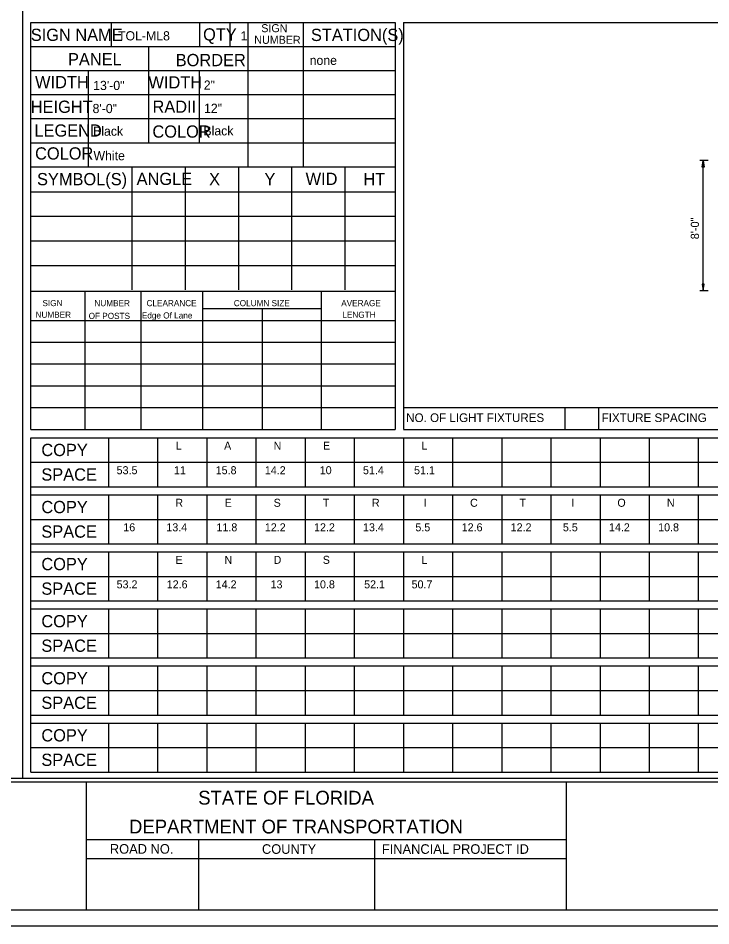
# Model space of a CAD drawing. Extents: x 122633 to 124574, y -23288 to -22025.
# Drawn here: x 123601 to 124110, y -23272 to -22604 of the extents above; entities that cross this region are included whole.
import ezdxf

# ---------------------------------------------------------------- set-up
doc = ezdxf.new("R2010")
doc.units = 0
for name, color, linetype in [('GSDims', 7, 'Continuous'), ('GSSign', 7, 'Continuous'), ('PlotBorder_dp', 7, 'Continuous'), ('SheetBorder_dp', 7, 'Continuous'), ('SheetLines_dp', 7, 'Continuous'), ('SheetLinesMisc2_dp', 7, 'Continuous'), ('TextMinor', 7, 'Continuous'), ('TextMisc', 7, 'Continuous')]:
    doc.layers.add(name, color=color, linetype=linetype)

msp = doc.modelspace()

# ---------------------------------------------------------------- linework, layer by layer
at = {"layer": 'GSDims'}
for p, q in [((124107.69, -22708.87), (124101.44, -22708.87)), ((124103.94, -22804.87), (124103.94, -22708.87)), ((124107.69, -22708.87), (124107.69, -22708.87)), ((124107.69, -22804.87), (124101.44, -22804.87)), ((124107.69, -22804.87), (124107.69, -22804.87))]:
    msp.add_line(p, q, dxfattribs=at)
for points in [[(124103.94, -22708.87), (124104.77, -22713.87), (124103.11, -22713.87)], [(124103.94, -22804.87), (124104.77, -22799.87), (124103.11, -22799.87)]]:
    msp.add_lwpolyline(points, close=True, dxfattribs=at)
at = {"layer": 'PlotBorder_dp'}
msp.add_lwpolyline([(122633.11, -23271.62), (124574.11, -23271.62), (124574.11, -22024.68), (122633.11, -22024.68)], close=True, dxfattribs=at)
at = {"layer": 'SheetBorder_dp'}
for p, q in [((122697.81, -23165.75), (124509.41, -23165.75)), ((122697.81, -23259.86), (124509.41, -23259.86))]:
    msp.add_line(p, q, dxfattribs=at)
at = {"layer": 'SheetLines_dp'}
for p, q in [((123650.66, -23165.75), (123650.66, -23259.86)), ((124003.57, -23259.86), (124003.57, -23165.75)), ((123650.66, -23208.1), (124003.57, -23208.1)), ((123733.01, -23208.1), (123733.01, -23259.86)), ((123862.41, -23208.1), (123862.41, -23259.86)), ((123650.66, -23222.22), (124003.57, -23222.22))]:
    msp.add_line(p, q, dxfattribs=at)
at = {"layer": 'SheetLinesMisc2_dp'}
for p, q in [((123603.64, -22039.22), (123603.64, -23162.98)), ((123609.83, -22906.62), (123609.83, -22607.55)), ((123609.83, -22607.55), (123877.5, -22607.55)), ((123668.83, -22607.55), (123668.83, -22625.22)), ((123733.89, -22607.55), (123733.89, -22625.22)), ((123756.12, -22607.55), (123756.12, -22625.22)), ((123769.37, -22607.55), (123769.37, -22713.54)), ((123810.1, -22607.55), (123810.1, -22713.54)), ((123877.5, -22607.55), (123877.5, -22906.62)), ((123883.65, -22607.55), (124497.63, -22607.55)), ((123883.65, -22607.55), (123883.65, -22906.19)), ((123609.83, -22625.22), (123877.5, -22625.22)), ((123696.33, -22625.22), (123696.33, -22696.07)), ((123609.83, -22642.88), (123877.5, -22642.88)), ((123652.13, -22642.88), (123652.13, -22713.54)), ((123733.66, -22643.07), (123733.66, -22696.07)), ((123609.83, -22660.55), (123877.5, -22660.55)), ((123609.83, -22678.21), (123877.5, -22678.21)), ((123609.83, -22695.88), (123709.1, -22695.88)), ((123696.33, -22696.07), (123769.37, -22696.07)), ((123769.37, -22695.88), (123877.5, -22695.88)), ((123609.83, -22713.54), (123877.5, -22713.54)), ((123684.16, -22713.89), (123684.16, -22804.08)), ((123723.27, -22713.89), (123723.27, -22804.08)), ((123762.39, -22713.89), (123762.39, -22804.08)), ((123801.49, -22713.89), (123801.49, -22804.08)), ((123840.61, -22713.89), (123840.61, -22804.08)), ((123609.88, -22731.93), (123877.5, -22731.93)), ((123609.88, -22749.97), (123877.5, -22749.97)), ((123609.88, -22768), (123877.5, -22768)), ((123609.88, -22786.04), (123877.5, -22786.04)), ((123609.83, -22804.95), (123877.5, -22804.95)), ((123649.54, -22804.95), (123649.54, -22906.62)), ((123690.6, -22804.95), (123690.6, -22906.62)), ((123735.93, -22804.95), (123735.93, -22906.62)), ((123823.22, -22804.95), (123823.22, -22906.62)), ((123735.93, -22817.88), (123823.16, -22817.88)), ((123779.75, -22817.88), (123779.75, -22906.62)), ((123609.83, -22826.5), (123877.5, -22826.5)), ((123609.83, -22842.52), (123877.5, -22842.52)), ((123609.83, -22858.55), (123877.5, -22858.55)), ((123609.83, -22874.57), (123877.5, -22874.57)), ((123609.83, -22890.6), (123877.5, -22890.6)), ((123883.65, -22890.59), (124497.63, -22890.59)), ((124002.24, -22890.59), (124002.24, -22906.61)), ((124027.09, -22890.59), (124027.09, -22906.61)), ((123609.83, -22906.62), (123877.5, -22906.62)), ((123883.65, -22906.19), (123883.65, -22906.59)), ((123883.65, -22906.61), (124497.63, -22906.61)), ((123609.8, -22912.77), (124497.63, -22912.77)), ((123609.8, -23158.6), (123609.8, -22912.77)), ((123666.96, -22912.77), (123666.96, -22948.85)), ((123703.08, -22912.77), (123703.08, -22948.85)), ((123739.18, -22912.77), (123739.18, -22948.85)), ((123775.3, -22912.77), (123775.3, -22948.85)), ((123811.43, -22912.77), (123811.43, -22948.85)), ((123847.54, -22912.77), (123847.54, -22948.85)), ((123883.65, -22912.77), (123883.65, -22948.85)), ((123919.77, -22912.77), (123919.77, -22948.85)), ((123955.89, -22912.77), (123955.89, -22948.85)), ((123992, -22912.77), (123992, -22948.85)), ((124028.13, -22912.77), (124028.13, -22948.85)), ((124064.23, -22912.77), (124064.23, -22948.85)), ((124100.35, -22912.77), (124100.35, -22948.85)), ((123609.8, -22930.8), (124497.63, -22930.8)), ((123609.8, -22948.85), (124497.63, -22948.85)), ((123609.8, -22954.73), (124497.63, -22954.73)), ((123666.96, -22954.73), (123666.96, -22990.8)), ((123703.08, -22954.73), (123703.08, -22990.8)), ((123739.18, -22954.73), (123739.18, -22990.8)), ((123775.3, -22954.73), (123775.3, -22990.8)), ((123811.43, -22954.73), (123811.43, -22990.8)), ((123847.54, -22954.73), (123847.54, -22990.8)), ((123883.65, -22954.73), (123883.65, -22990.8)), ((123919.77, -22954.73), (123919.77, -22990.8)), ((123955.89, -22954.73), (123955.89, -22990.8)), ((123992, -22954.73), (123992, -22990.8)), ((124028.13, -22954.73), (124028.13, -22990.8)), ((124064.23, -22954.73), (124064.23, -22990.8)), ((124100.35, -22954.73), (124100.35, -22990.8)), ((123609.8, -22972.77), (124497.63, -22972.77)), ((123609.8, -22990.8), (124497.63, -22990.8)), ((123609.8, -22996.68), (124497.63, -22996.68)), ((123666.96, -22996.68), (123666.96, -23032.75)), ((123703.08, -22996.68), (123703.08, -23032.75)), ((123739.18, -22996.68), (123739.18, -23032.75)), ((123775.3, -22996.68), (123775.3, -23032.75)), ((123811.43, -22996.68), (123811.43, -23032.75)), ((123847.54, -22996.68), (123847.54, -23032.75)), ((123883.65, -22996.68), (123883.65, -23032.75)), ((123919.77, -22996.68), (123919.77, -23032.75)), ((123955.89, -22996.68), (123955.89, -23032.75)), ((123992, -22996.68), (123992, -23032.75)), ((124028.13, -22996.68), (124028.13, -23032.75)), ((124064.23, -22996.68), (124064.23, -23032.75)), ((124100.35, -22996.68), (124100.35, -23032.75)), ((123609.8, -23014.71), (124497.63, -23014.71)), ((123609.8, -23032.75), (124497.63, -23032.75)), ((123609.8, -23038.63), (124497.63, -23038.63)), ((123666.96, -23038.63), (123666.96, -23074.71)), ((123703.08, -23038.63), (123703.08, -23074.71)), ((123739.18, -23038.63), (123739.18, -23074.71)), ((123775.3, -23038.63), (123775.3, -23074.71)), ((123811.43, -23038.63), (123811.43, -23074.71)), ((123847.54, -23038.63), (123847.54, -23074.71)), ((123883.65, -23038.63), (123883.65, -23074.71)), ((123919.77, -23038.63), (123919.77, -23074.71)), ((123955.89, -23038.63), (123955.89, -23074.71)), ((123992, -23038.63), (123992, -23074.71)), ((124028.13, -23038.63), (124028.13, -23074.71)), ((124064.23, -23038.63), (124064.23, -23074.71)), ((124100.35, -23038.63), (124100.35, -23074.71)), ((123609.8, -23056.66), (124497.63, -23056.66)), ((123609.8, -23074.71), (124497.63, -23074.71)), ((123609.8, -23080.59), (124497.63, -23080.59)), ((123666.96, -23080.59), (123666.96, -23116.66)), ((123703.08, -23080.59), (123703.08, -23116.66)), ((123739.18, -23080.59), (123739.18, -23116.66)), ((123775.3, -23080.59), (123775.3, -23116.66)), ((123811.43, -23080.59), (123811.43, -23116.66)), ((123847.54, -23080.59), (123847.54, -23116.66)), ((123883.65, -23080.59), (123883.65, -23116.66)), ((123919.77, -23080.59), (123919.77, -23116.66)), ((123955.89, -23080.59), (123955.89, -23116.66)), ((123992, -23080.59), (123992, -23116.66)), ((124028.13, -23080.59), (124028.13, -23116.66)), ((124064.23, -23080.59), (124064.23, -23116.66)), ((124100.35, -23080.59), (124100.35, -23116.66)), ((123609.8, -23098.63), (124497.63, -23098.63)), ((123609.8, -23116.66), (124497.63, -23116.66)), ((123609.8, -23122.54), (124497.63, -23122.54)), ((123666.96, -23122.54), (123666.96, -23158.6)), ((123703.08, -23122.54), (123703.08, -23158.6)), ((123739.18, -23122.54), (123739.18, -23158.6)), ((123775.3, -23122.54), (123775.3, -23158.6)), ((123811.43, -23122.54), (123811.43, -23158.6)), ((123847.54, -23122.54), (123847.54, -23158.6)), ((123883.65, -23122.54), (123883.65, -23158.6)), ((123919.77, -23122.54), (123919.77, -23158.6)), ((123955.89, -23122.54), (123955.89, -23158.6)), ((123992, -23122.54), (123992, -23158.6)), ((124028.13, -23122.54), (124028.13, -23158.6)), ((124064.23, -23122.54), (124064.23, -23158.6)), ((124100.35, -23122.54), (124100.35, -23158.6)), ((123609.8, -23140.57), (124497.63, -23140.57)), ((123609.8, -23158.6), (124497.63, -23158.6)), ((122701.01, -23162.98), (124506.26, -23162.98))]:
    msp.add_line(p, q, dxfattribs=at)

# ---------------------------------------------------------------- texts
at = {"layer": 'GSDims'}
msp.add_text('8\'-0"', height=6, rotation=90, dxfattribs=at).set_placement((124100.83, -22766.87))
at = {"layer": 'GSSign'}
for s, height, p in [('TOL-ML8', 6.749, (123673.96, -22620.68)), ('1', 6.75, (123764.05, -22620.7)), ('none', 6.749, (123814.77, -22638.7)), ('13\'-0"', 6.749, (123655.71, -22657.16)), ('2"', 6.749, (123736.97, -22656.91)), ('8\'-0"', 6.749, (123655.25, -22674.12)), ('12"', 6.749, (123737.15, -22673.93)), ('Black', 6.749, (123655.63, -22690.76)), ('Black', 6.749, (123736.7, -22690.5)), ('White', 6.749, (123655.93, -22708.81)), ('L', 5.88, (123716.33, -22921.58)), ('A', 5.88, (123751.89, -22921.58)), ('N', 5.88, (123788.29, -22921.58)), ('E', 5.88, (123824.56, -22921.58)), ('L', 5.88, (123896.95, -22921.58)), ('53.5', 5.882, (123672.92, -22939.61)), ('11', 5.882, (123715.07, -22939.61)), ('15.8', 5.882, (123745.73, -22939.61)), ('14.2', 5.882, (123781.85, -22939.61)), ('10', 5.882, (123822.18, -22939.61)), ('51.4', 5.882, (123853.96, -22939.61)), ('51.1', 5.882, (123891.49, -22939.61)), ('R', 5.88, (123716.05, -22963.53)), ('E', 5.88, (123752.31, -22963.53)), ('S', 5.88, (123788.29, -22963.53)), ('T', 5.88, (123824.42, -22963.53)), ('R', 5.88, (123860.54, -22963.53)), ('I', 5.88, (123898.63, -22963.53)), ('C', 5.88, (123932.65, -22963.53)), ('T', 5.88, (123968.92, -22963.53)), ('I', 5.88, (124007, -22963.53)), ('O', 5.88, (124040.89, -22963.53)), ('N', 5.88, (124077.29, -22963.53)), ('16', 5.882, (123677.82, -22981.57)), ('13.4', 5.882, (123709.46, -22981.57)), ('11.8', 5.882, (123746.29, -22981.57)), ('12.2', 5.882, (123781.85, -22981.57)), ('12.2', 5.882, (123817.98, -22981.57)), ('13.4', 5.882, (123853.96, -22981.57)), ('5.5', 5.882, (123892.47, -22981.57)), ('12.6', 5.882, (123926.49, -22981.57)), ('12.2', 5.882, (123962.47, -22981.57)), ('5.5', 5.882, (124000.84, -22981.57)), ('14.2', 5.882, (124034.72, -22981.57)), ('10.8', 5.882, (124070.85, -22981.57)), ('E', 5.88, (123716.19, -23005.49)), ('N', 5.88, (123752.17, -23005.49)), ('D', 5.88, (123788.29, -23005.49)), ('S', 5.88, (123824.42, -23005.49)), ('L', 5.88, (123896.95, -23005.49)), ('53.2', 5.882, (123672.92, -23023.52)), ('12.6', 5.882, (123709.74, -23023.52)), ('14.2', 5.882, (123745.73, -23023.52)), ('13', 5.882, (123786.05, -23023.52)), ('10.8', 5.882, (123817.98, -23023.52)), ('52.1', 5.882, (123854.8, -23023.52)), ('50.7', 5.882, (123889.67, -23023.52))]:
    msp.add_text(s, height=height, dxfattribs=at).set_placement(p)
at = {"layer": 'TextMinor'}
for s, height, p in [('SIGN NAME', 8.999, (123609.83, -22621.08)), ('QTY', 8.999, (123736.46, -22620.78)), ('SIGN', 5.882, (123779.2, -22614.63)), ('STATION(S)', 8.999, (123815.71, -22621.13)), ('NUMBER', 5.882, (123774.08, -22623.19)), ('PANEL', 8.999, (123637.19, -22639.02)), ('BORDER', 8.999, (123716.34, -22639.63)), ('WIDTH', 8.999, (123613, -22655.84)), ('WIDTH', 8.999, (123696.33, -22656.02)), ('HEIGHT', 8.999, (123609.83, -22673.95)), ('RADII', 8.999, (123699.29, -22673.92)), ('LEGEND', 8.999, (123612.53, -22691.42)), ('COLOR', 8.999, (123699.22, -22692.18)), ('COLOR', 8.999, (123613, -22708.27)), ('SYMBOL(S)', 8.999, (123614.43, -22727.16)), ('ANGLE', 8.999, (123687.6, -22726.97)), ('X', 9, (123740.87, -22727.16)), ('Y', 9, (123781.54, -22727.16)), ('WID', 8.999, (123811.82, -22726.97)), ('HT', 8.999, (123854.22, -22727.14)), ('SIGN', 4.5, (123618.41, -22816.04)), ('NUMBER', 4.5, (123656.61, -22816.1)), ('CLEARANCE', 4.5, (123694.92, -22816.07)), ('COLUMN SIZE', 4.4996, (123759.04, -22816.07)), ('AVERAGE', 4.5, (123837.97, -22816.07)), ('NUMBER', 4.5, (123613.36, -22824.6)), ('OF POSTS', 4.5, (123652.36, -22825.45)), ('Edge Of Lane', 4.4996, (123691.45, -22825.12)), ('LENGTH', 4.5, (123838.82, -22824.6)), ('NO. OF LIGHT FIXTURES', 6.3774, (123885.71, -22901.25)), ('FIXTURE SPACING', 6.3774, (124029.3, -22901.25)), ('COPY', 8.999, (123617.61, -22926.26)), ('SPACE', 8.999, (123617.61, -22944.3)), ('COPY', 8.999, (123617.61, -22968.23)), ('SPACE', 8.999, (123617.61, -22986.26)), ('COPY', 8.999, (123617.61, -23010.16)), ('SPACE', 8.999, (123617.61, -23028.2)), ('COPY', 8.999, (123617.61, -23052.13)), ('SPACE', 8.999, (123617.61, -23070.16)), ('COPY', 8.999, (123617.61, -23094.09)), ('SPACE', 8.999, (123617.61, -23112.12)), ('COPY', 8.999, (123617.61, -23136.04)), ('SPACE', 8.999, (123617.61, -23154.06))]:
    msp.add_text(s, height=height, dxfattribs=at).set_placement(p)
at = {"layer": 'TextMisc'}
for s, height, p in [('STATE OF FLORIDA', 10.1637, (123732.88, -23182.49)), ('DEPARTMENT OF TRANSPORTATION', 10.1637, (123682.04, -23203.73)), ('ROAD NO.', 7.058, (123667.96, -23218.57)), ('COUNTY', 7.058, (123779.71, -23218.69)), ('FINANCIAL PROJECT ID', 7.0582, (123867.82, -23218.69))]:
    msp.add_text(s, height=height, dxfattribs=at).set_placement(p)

doc.saveas('drawing.dxf')
